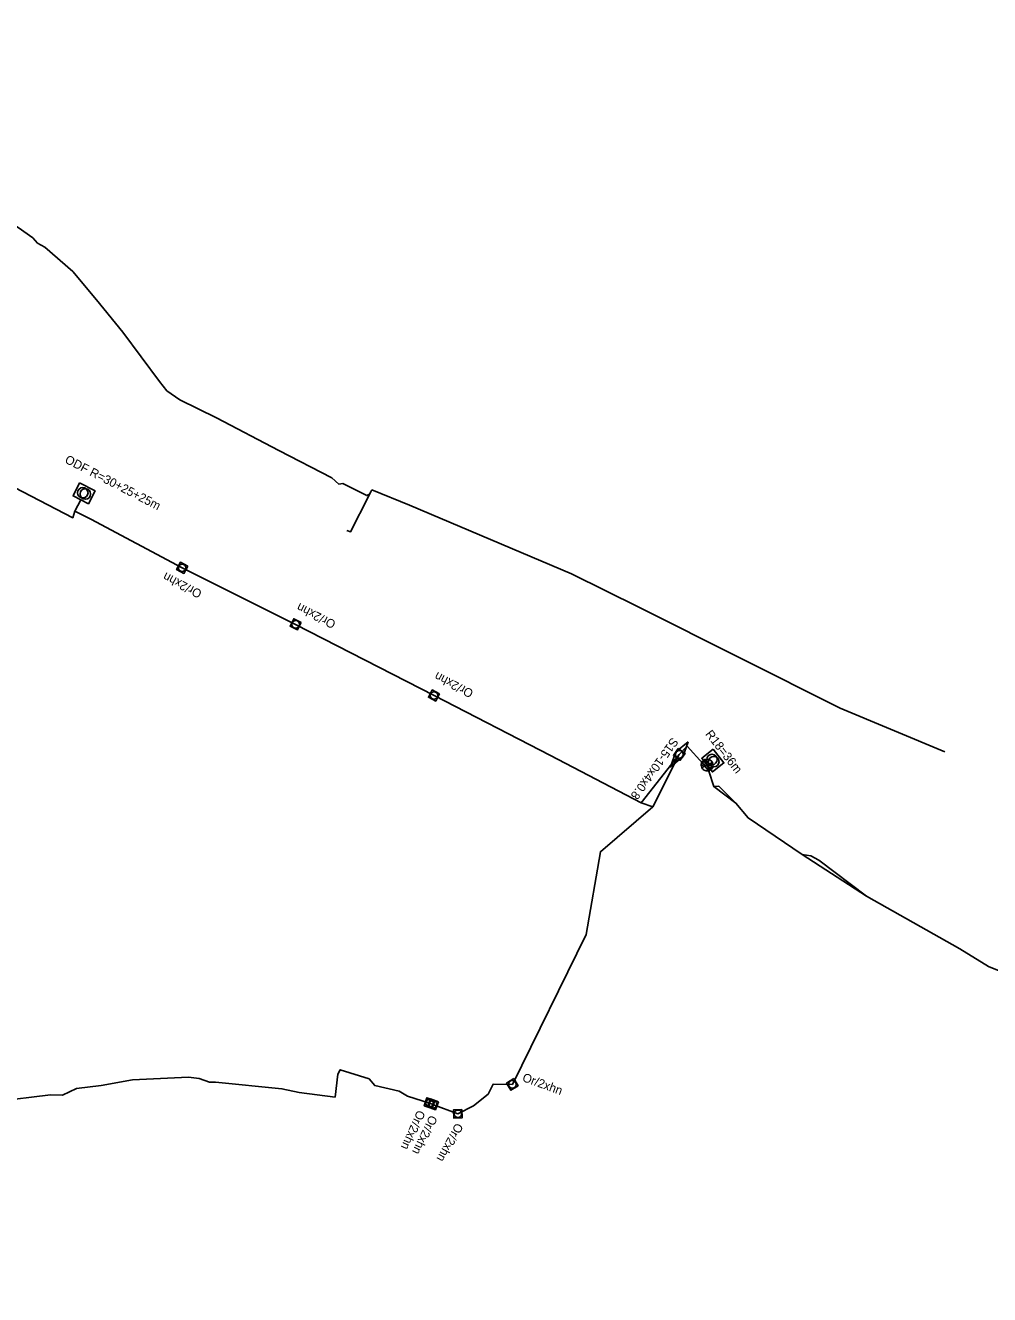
# Model space of a CAD drawing. Extents: x -748507 to -687366, y -1057342 to -1024924.
# Drawn here: x -748101.2 to -747880.2, y -1025489.9 to -1025198.9 of the extents above; entities that cross this region are included whole.
import ezdxf

# ---------------------------------------------------------------- set-up
doc = ezdxf.new("R2010")
doc.units = 0
doc.layers.add('Telefonica O2', color=7, linetype='Continuous')
doc.layers.add('TK+DOK_Pha Holešovice - Kralupy', color=7, linetype='Continuous')

msp = doc.modelspace()

# ---------------------------------------------------------------- linework, layer by layer
at = {"layer": 'Telefonica O2'}
for points in [[(-748099.49, -1025247.61), (-748102.85, -1025245.24), (-748107.48, -1025242.31), (-748109.5, -1025241.07), (-748118.75, -1025236.3), (-748125.3, -1025233.33), (-748126.31, -1025232.55), (-748136.87, -1025226.88), (-748148.96, -1025220.66), (-748151.17, -1025220.06), (-748151.9, -1025219.17), (-748164.97, -1025212.45), (-748180.6, -1025204.46), (-748182.39, -1025202.15), (-748182.58, -1025198.88)], [(-748022.32, -1025306.38), (-748022.89, -1025306.69), (-748028.45, -1025303.92), (-748029.36, -1025304.03), (-748030.95, -1025302.64), (-748043.09, -1025296.33), (-748057.41, -1025288.89), (-748065.75, -1025284.73), (-748068.74, -1025282.66), (-748070.44, -1025280.54), (-748078.84, -1025269.2), (-748084.89, -1025261.77), (-748090.29, -1025255.34), (-748096.71, -1025249.74), (-748098.39, -1025248.78), (-748099.49, -1025247.61)], [(-748022.32, -1025306.38), (-748021.98, -1025305.82)], [(-748021.74, -1025305.39), (-748021.98, -1025305.82)], [(-747890.5, -1025365.42), (-747914.48, -1025355.42), (-747960.44, -1025332.34), (-747976.03, -1025324.63), (-748013.13, -1025308.89), (-748021.74, -1025305.39)], [(-748027.5, -1025314.66), (-748026.63, -1025314.99), (-748022.44, -1025306.73), (-748022.32, -1025306.38)], [(-748026.63, -1025314.99), (-748022.44, -1025306.73)]]:
    msp.add_lwpolyline(points, dxfattribs=at)
at = {"layer": 'TK+DOK_Pha Holešovice - Kralupy'}
for p, q in [((-748087.27, -1025305.1), (-748087.23, -1025305.13)), ((-747942.76, -1025366.66), (-747942.74, -1025366.7)), ((-747946.28, -1025368.64), (-747945.1, -1025368.11)), ((-747946.2, -1025367.98), (-747945.33, -1025367.59)), ((-747946.18, -1025369), (-747946.18, -1025369)), ((-747946.18, -1025369), (-747946.18, -1025369)), ((-747944.81, -1025368.75), (-747943.61, -1025368.22)), ((-747944.57, -1025369.27), (-747943.66, -1025368.86)), ((-747944.38, -1025369.69), (-747944.38, -1025369.69)), ((-747943.71, -1025367.9), (-747943.71, -1025367.9)), ((-747943.71, -1025367.9), (-747943.71, -1025367.9))]:
    msp.add_line(p, q, dxfattribs=at)
for points in [[(-748089.81, -1025310.23), (-748090.31, -1025311.78), (-748120.93, -1025295.87), (-748145.26, -1025283.44), (-748175.8, -1025267.75), (-748197.48, -1025255.01), (-748198.7, -1025254.01), (-748229.45, -1025234.94), (-748248.68, -1025224.4)], [(-747951.32, -1025366.02), (-747960.05, -1025377.15), (-747980.82, -1025366.29), (-748007.53, -1025352.51), (-748039.24, -1025336.2), (-748065.25, -1025323.24), (-748086.15, -1025312.1), (-748089.81, -1025310.23), (-748088.49, -1025307.65)], [(-747949.52, -1025364.16), (-747951.32, -1025366.02), (-747957.41, -1025378.06), (-747960.05, -1025377.15), (-747980.82, -1025366.29), (-748007.53, -1025352.51), (-748039.24, -1025336.2), (-748065.25, -1025323.24), (-748086.15, -1025312.1), (-748089.81, -1025310.23), (-748088.49, -1025307.65)], [(-747949.29, -1025363.17), (-747950.51, -1025366.6), (-747953.35, -1025368.87), (-747952.14, -1025365.44), (-747949.29, -1025363.17)], [(-747748.86, -1025489.87), (-747775.24, -1025474.76), (-747803.17, -1025458.25), (-747811.63, -1025453.7), (-747828.77, -1025443.84), (-747837.67, -1025438.3), (-747838.64, -1025437.29), (-747846.18, -1025433.45), (-747848.07, -1025433.59), (-747855.58, -1025428.86), (-747872.87, -1025417.7), (-747880.45, -1025414.61), (-747887.01, -1025410.62), (-747908.41, -1025398.49), (-747923.18, -1025388.98), (-747935.54, -1025380.57), (-747938.34, -1025377.23), (-747942.24, -1025373.31), (-747943.41, -1025373.4), (-747944.55, -1025369.86), (-747945.89, -1025368.09), (-747949.52, -1025364.16), (-747951.32, -1025366.02)], [(-747872.87, -1025417.7), (-747880.45, -1025414.61), (-747887.01, -1025410.62), (-747908.41, -1025398.49), (-747919.32, -1025390.28), (-747921.14, -1025389.25), (-747923.18, -1025388.98), (-747935.54, -1025380.57), (-747938.34, -1025377.23), (-747943.41, -1025373.4), (-747944.55, -1025369.86), (-747945.89, -1025368.09), (-747949.52, -1025364.16)], [(-747945.48, -1025367.22), (-747944.95, -1025368.46), (-747946.18, -1025369)], [(-747943.71, -1025367.9), (-747944.94, -1025368.46), (-747944.38, -1025369.69)], [(-747957.41, -1025378.06), (-747969.41, -1025388.33), (-747972.65, -1025407.29), (-747989.57, -1025441.68), (-747993.95, -1025441.62), (-747995.15, -1025443.94)], [(-747995.15, -1025443.94), (-747998.5, -1025446.58), (-748002.06, -1025448.41), (-748007.77, -1025446.26), (-748008.55, -1025445.97), (-748013.6, -1025444.41), (-748015.51, -1025443.2), (-748021.12, -1025441.96), (-748022.42, -1025440.41), (-748029.02, -1025438.3), (-748029.55, -1025439.33), (-748030.19, -1025444.59), (-748038.41, -1025443.52), (-748042.4, -1025442.69), (-748057.58, -1025441.16), (-748059, -1025441.17), (-748061.32, -1025440.3), (-748063.82, -1025440), (-748076.62, -1025440.63), (-748083.81, -1025441.9), (-748089.45, -1025442.62), (-748092.68, -1025444.14), (-748095.38, -1025444.07), (-748107.92, -1025445.58)]]:
    msp.add_lwpolyline(points, dxfattribs=at)
for points in [[(-748088.74, -1025303.79), (-748085.2, -1025305.61), (-748086.72, -1025308.56), (-748090.26, -1025306.74)], [(-748063.96, -1025322.83), (-748065.66, -1025321.95), (-748066.54, -1025323.65), (-748064.84, -1025324.53)], [(-748037.95, -1025335.78), (-748039.66, -1025334.91), (-748040.53, -1025336.62), (-748038.82, -1025337.49)], [(-748006.24, -1025352.1), (-748007.94, -1025351.22), (-748008.82, -1025352.92), (-748007.12, -1025353.8)], [(-747951.55, -1025364.68), (-747952.66, -1025366.24), (-747951.09, -1025367.36), (-747949.98, -1025365.8)], [(-747943.55, -1025364.84), (-747941.09, -1025367.98), (-747943.71, -1025370.03), (-747946.16, -1025366.89)], [(-747989.25, -1025440.36), (-747990.89, -1025441.36), (-747989.89, -1025443), (-747988.25, -1025442)], [(-748007.33, -1025445.37), (-748009.15, -1025444.75), (-748009.77, -1025446.57), (-748007.95, -1025447.19)], [(-748006.53, -1025445.7), (-748008.33, -1025445.02), (-748009.01, -1025446.82), (-748007.21, -1025447.5)], [(-748001.16, -1025447.4), (-748003.07, -1025447.51), (-748002.96, -1025449.42), (-748001.05, -1025449.31)]]:
    msp.add_lwpolyline(points, close=True, dxfattribs=at)
for centre, radius in [((-748088.02, -1025306.03), 1.2), ((-748087.43, -1025306.31), 1.2), ((-748065.25, -1025323.24), 0.864), ((-748039.24, -1025336.2), 0.864), ((-748007.53, -1025352.51), 0.864), ((-747951.32, -1025366.02), 0.864), ((-747943.83, -1025367.19), 1.2), ((-747943.41, -1025367.69), 1.2), ((-747989.57, -1025441.68), 0.864), ((-748008.55, -1025445.97), 0.864), ((-748007.77, -1025446.26), 0.864), ((-748002.06, -1025448.41), 0.864)]:
    msp.add_circle(centre, radius, dxfattribs=at)
for centre, start, end in [((-747944.94, -1025368.46), 113.4961, 203.7332), ((-747944.93, -1025368.46), 24.4484, 113.8144), ((-747944.94, -1025368.46), 203.7345, 294.5239), ((-747944.93, -1025368.46), 294.2113, 24.4484)]:
    msp.add_arc(centre, 1.35, start, end, dxfattribs=at)

# ---------------------------------------------------------------- texts
for s, rotation, p in [('ODF R=30+25+25m', 332.7963, (-748092.31, -1025299.05)), ('Or/2xhn', 152.728, (-748060.53, -1025328.57)), ('Or/2xhn', 153.1477, (-748029.86, -1025335.53)), ('Or/2xhn', 152.7456, (-747998.32, -1025351.4)), ('R18=36m', 308.0244, (-747945.47, -1025361.4)), ('S15-10x4x0.8', 234.5547, (-747953, -1025361.99)), ('Or/2xhn', 339.8641, (-747987.45, -1025440.87)), ('Or/2xhn', 245.7269, (-748011.27, -1025447.41)), ('Or/2xhn', 243.9759, (-748008.44, -1025448.58)), ('Or/2xhn', 241.4663, (-748002.48, -1025450.36))]:
    msp.add_text(s, height=2, rotation=rotation, dxfattribs=at).set_placement(p)

doc.saveas('drawing.dxf')
